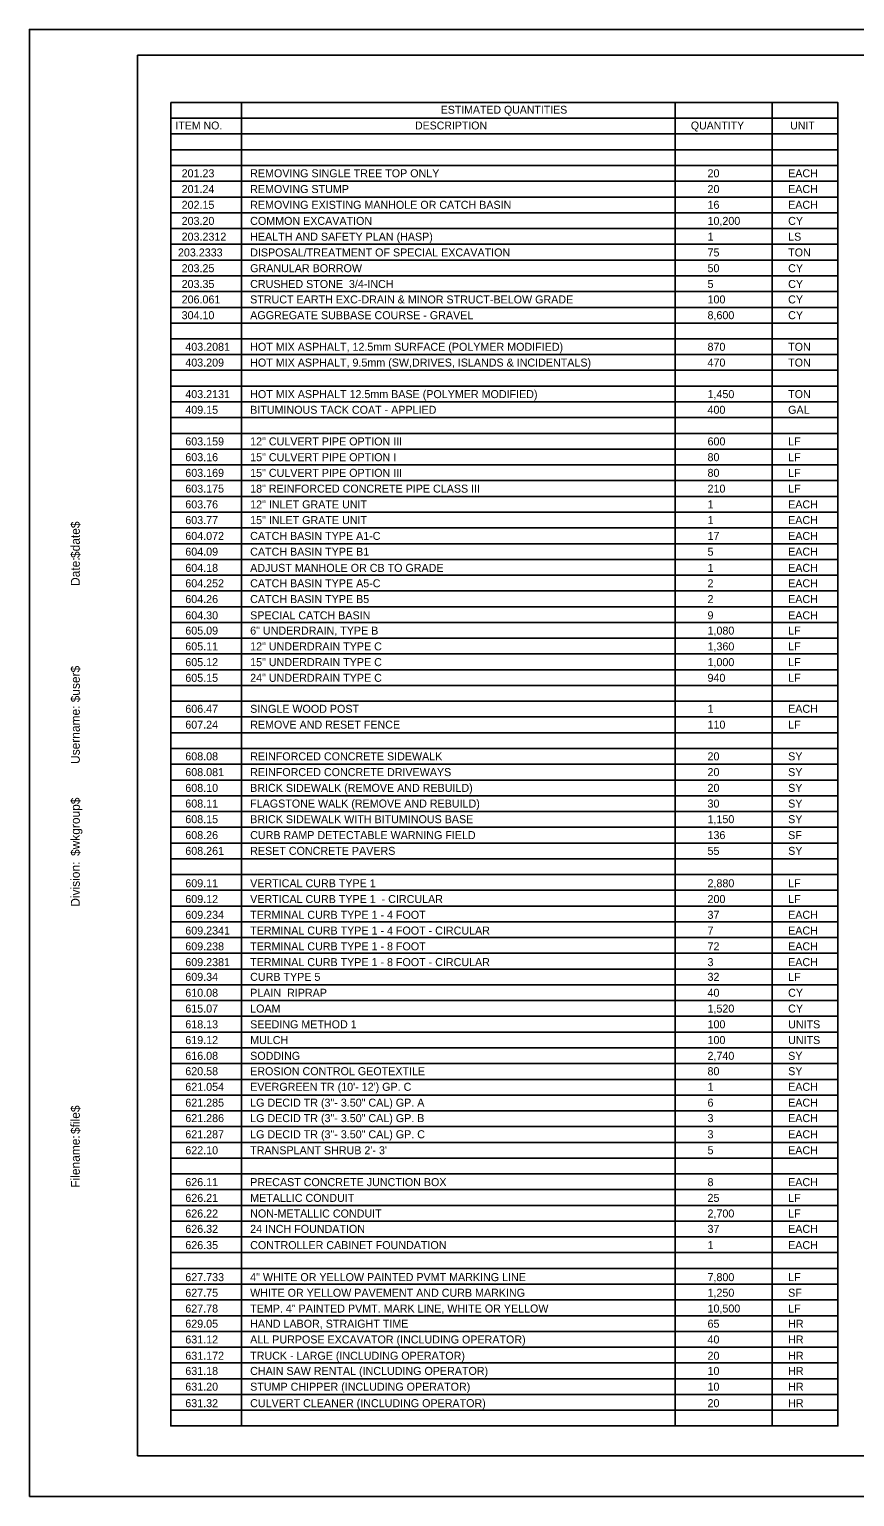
# Model space of a CAD drawing. Extents: x -0.13 to 2.7, y -0.05 to 1.78.
# Drawn here: x -0.135 to 0.896, y -0.051 to 1.782 of the extents above; entities that cross this region are included whole.
import ezdxf

# ---------------------------------------------------------------- set-up
doc = ezdxf.new("R2010")
doc.units = 0
for name, color, linetype in [('ANNOTATION', 7, 'Continuous'), ('BORDER', 7, 'Continuous'), ('PLOT BOUNDARY', 7, 'Continuous')]:
    doc.layers.add(name, color=color, linetype=linetype)

msp = doc.modelspace()

# ---------------------------------------------------------------- linework, layer by layer
at = {"layer": 'BORDER'}
for p, q in [((2.6667, 1.75), (0, 1.75)), ((0, 1.75), (0, 0)), ((0.1302, 1.6909), (0.1302, 0.0373)), ((0.6716, 1.6909), (0.6716, 0.0373)), ((0.793, 1.6909), (0.793, 0.0373)), ((0.0417, 1.6713), (0.875, 1.6713)), ((0.0417, 1.6516), (0.875, 1.6516)), ((0.0417, 1.6319), (0.875, 1.6319)), ((0.0417, 1.6122), (0.875, 1.6122)), ((0.0417, 1.5925), (0.875, 1.5925)), ((0.0417, 1.5728), (0.875, 1.5728)), ((0.0417, 1.5531), (0.875, 1.5531)), ((0.0417, 1.5335), (0.875, 1.5335)), ((0.0417, 1.5138), (0.875, 1.5138)), ((0.0417, 1.4941), (0.875, 1.4941)), ((0.0417, 1.4744), (0.875, 1.4744)), ((0.0417, 1.4547), (0.875, 1.4547)), ((0.0417, 1.435), (0.875, 1.435)), ((0.0417, 1.4153), (0.875, 1.4153)), ((0.0417, 1.3957), (0.875, 1.3957)), ((0.0417, 1.376), (0.875, 1.376)), ((0.0417, 1.3563), (0.875, 1.3563)), ((0.0417, 1.3366), (0.875, 1.3366)), ((0.0417, 1.3169), (0.875, 1.3169)), ((0.0417, 1.2972), (0.875, 1.2972)), ((0.0417, 1.2775), (0.875, 1.2775)), ((0.0417, 1.2579), (0.875, 1.2579)), ((0.0417, 1.2382), (0.875, 1.2382)), ((0.0417, 1.2185), (0.875, 1.2185)), ((0.0417, 1.1988), (0.875, 1.1988)), ((0.0417, 1.1791), (0.875, 1.1791)), ((0.0417, 1.1594), (0.875, 1.1594)), ((0.0417, 1.1397), (0.875, 1.1397)), ((0.0417, 1.12), (0.875, 1.12)), ((0.0417, 1.1004), (0.875, 1.1004)), ((0.0417, 1.0807), (0.875, 1.0807)), ((0.0417, 1.061), (0.875, 1.061)), ((0.0417, 1.0413), (0.875, 1.0413)), ((0.0417, 1.0216), (0.875, 1.0216)), ((0.0417, 1.0019), (0.875, 1.0019)), ((0.0417, 0.9822), (0.875, 0.9822)), ((0.0417, 0.9626), (0.875, 0.9626)), ((0.0417, 0.9429), (0.875, 0.9429)), ((0.0417, 0.9232), (0.875, 0.9232)), ((0.0417, 0.9035), (0.875, 0.9035)), ((0.0417, 0.8838), (0.875, 0.8838)), ((0.0417, 0.8641), (0.875, 0.8641)), ((0.0417, 0.8444), (0.875, 0.8444)), ((0.0417, 0.8248), (0.875, 0.8248)), ((0.0417, 0.8051), (0.875, 0.8051)), ((0.0417, 0.7854), (0.875, 0.7854)), ((0.0417, 0.7657), (0.875, 0.7657)), ((0.0417, 0.746), (0.875, 0.746)), ((0.0417, 0.7263), (0.875, 0.7263)), ((0.0417, 0.7066), (0.875, 0.7066)), ((0.0417, 0.687), (0.875, 0.687)), ((0.0417, 0.6673), (0.875, 0.6673)), ((0.0417, 0.6476), (0.875, 0.6476)), ((0.0417, 0.6279), (0.875, 0.6279)), ((0.0417, 0.6082), (0.875, 0.6082)), ((0.0417, 0.5885), (0.875, 0.5885)), ((0.0417, 0.5688), (0.875, 0.5688)), ((0.0417, 0.5492), (0.875, 0.5492)), ((0.0417, 0.5295), (0.875, 0.5295)), ((0.0417, 0.5098), (0.875, 0.5098)), ((0.0417, 0.4901), (0.875, 0.4901)), ((0.0417, 0.4704), (0.875, 0.4704)), ((0.0417, 0.4507), (0.875, 0.4507)), ((0.0417, 0.431), (0.875, 0.431)), ((0.0417, 0.4114), (0.875, 0.4114)), ((0.0417, 0.3917), (0.875, 0.3917)), ((0.0417, 0.372), (0.875, 0.372)), ((0.0417, 0.3523), (0.875, 0.3523)), ((0.0417, 0.3326), (0.875, 0.3326)), ((0.0417, 0.3129), (0.875, 0.3129)), ((0.0417, 0.2932), (0.875, 0.2932)), ((0.0417, 0.2736), (0.875, 0.2736)), ((0.0417, 0.2539), (0.875, 0.2539)), ((0.0417, 0.2342), (0.875, 0.2342)), ((0.0417, 0.2145), (0.875, 0.2145)), ((0.0417, 0.1948), (0.875, 0.1948)), ((0.0417, 0.1751), (0.875, 0.1751)), ((0.0417, 0.1554), (0.875, 0.1554)), ((0.0417, 0.1357), (0.875, 0.1357)), ((0.0417, 0.1161), (0.875, 0.1161)), ((0.0417, 0.0964), (0.875, 0.0964)), ((0.0417, 0.0767), (0.875, 0.0767)), ((0.0417, 0.057), (0.875, 0.057)), ((0, 0), (2.6667, 0))]:
    msp.add_line(p, q, dxfattribs=at)
msp.add_lwpolyline([(0.0417, 1.6909), (0.875, 1.6909), (0.875, 0.0373), (0.0417, 0.0373)], close=True, dxfattribs=at)
at = {"layer": 'PLOT BOUNDARY'}
msp.add_lwpolyline([(-0.1349, -0.051), (2.6984, -0.051), (2.6984, 1.7823), (-0.1349, 1.7823)], close=True, dxfattribs=at)

# ---------------------------------------------------------------- texts
at = {"layer": 'ANNOTATION'}
for s, p in [('201.23', (0.0553, 1.5975)), ('REMOVING SINGLE TREE TOP ONLY', (0.1409, 1.5975)), ('20', (0.7121, 1.5975)), ('EACH', (0.8128, 1.5975)), ('201.24', (0.0553, 1.5778)), ('REMOVING STUMP', (0.1409, 1.5778)), ('20', (0.7121, 1.5778)), ('EACH', (0.8128, 1.5778)), ('202.15', (0.0553, 1.5581)), ('REMOVING EXISTING MANHOLE OR CATCH BASIN', (0.1409, 1.5581)), ('16', (0.7121, 1.5581)), ('EACH', (0.8128, 1.5581)), ('203.20', (0.0553, 1.538)), ('COMMON EXCAVATION', (0.1409, 1.538)), ('10,200', (0.7121, 1.538)), ('CY', (0.8128, 1.538)), ('203.2312', (0.0553, 1.5183)), ('HEALTH AND SAFETY PLAN (HASP)', (0.1409, 1.5183)), ('1', (0.7121, 1.5183)), ('LS', (0.8128, 1.5183)), ('203.2333', (0.0507, 1.4986)), ('DISPOSAL/TREATMENT OF SPECIAL EXCAVATION', (0.1409, 1.4986)), ('75', (0.7121, 1.4986)), ('TON', (0.8128, 1.4986)), ('203.25', (0.0553, 1.4789)), ('GRANULAR BORROW', (0.1409, 1.4789)), ('50', (0.7121, 1.4789)), ('CY', (0.8128, 1.4789)), ('203.35', (0.0553, 1.4592)), ('CRUSHED STONE  3/4-INCH', (0.1409, 1.4592)), ('5', (0.7121, 1.4592)), ('CY', (0.8128, 1.4592)), ('206.061', (0.0553, 1.4399)), ('STRUCT EARTH EXC-DRAIN & MINOR STRUCT-BELOW GRADE', (0.1409, 1.4399)), ('100', (0.7121, 1.4399)), ('CY', (0.8128, 1.4399)), ('304.10', (0.0553, 1.4202)), ('AGGREGATE SUBBASE COURSE - GRAVEL', (0.1409, 1.4202)), ('8,600', (0.7121, 1.4202)), ('CY', (0.8128, 1.4202)), ('403.2081', (0.0599, 1.3807)), ('HOT MIX ASPHALT, 12.5mm SURFACE (POLYMER MODIFIED)', (0.1409, 1.3807)), ('870', (0.7121, 1.3807)), ('TON', (0.8128, 1.3807)), ('403.209', (0.0599, 1.361)), ('HOT MIX ASPHALT, 9.5mm (SW,DRIVES, ISLANDS & INCIDENTALS)', (0.1409, 1.361)), ('470', (0.7121, 1.361)), ('TON', (0.8128, 1.361)), ('403.2131', (0.0599, 1.3216)), ('HOT MIX ASPHALT 12.5mm BASE (POLYMER MODIFIED)', (0.1409, 1.3216)), ('1,450', (0.7121, 1.3216)), ('TON', (0.8128, 1.3216)), ('409.15', (0.0599, 1.302)), ('BITUMINOUS TACK COAT - APPLIED', (0.1409, 1.302)), ('400', (0.7121, 1.302)), ('GAL', (0.8128, 1.302)), ('603.159', (0.0599, 1.2625)), ('12" CULVERT PIPE OPTION III', (0.1409, 1.2625)), ('600', (0.7121, 1.2625)), ('LF', (0.8128, 1.2625)), ('603.16', (0.0599, 1.2428)), ('15" CULVERT PIPE OPTION I', (0.1409, 1.2428)), ('80', (0.7121, 1.2428)), ('LF', (0.8128, 1.2428)), ('603.169', (0.0599, 1.2232)), ('15" CULVERT PIPE OPTION III', (0.1409, 1.2232)), ('80', (0.7121, 1.2232)), ('LF', (0.8128, 1.2232)), ('603.175', (0.0599, 1.2035)), ('18" REINFORCED CONCRETE PIPE CLASS III', (0.1409, 1.2035)), ('210', (0.7121, 1.2035)), ('LF', (0.8128, 1.2035)), ('603.76', (0.0599, 1.1838)), ('12" INLET GRATE UNIT', (0.1409, 1.1838)), ('1', (0.7121, 1.1838)), ('EACH', (0.8128, 1.1838)), ('603.77', (0.0599, 1.1642)), ('15" INLET GRATE UNIT', (0.1409, 1.1642)), ('1', (0.7121, 1.1642)), ('EACH', (0.8128, 1.1642)), ('604.072', (0.0599, 1.1444)), ('CATCH BASIN TYPE A1-C', (0.1409, 1.1444)), ('17', (0.7121, 1.1444)), ('EACH', (0.8128, 1.1444)), ('604.09', (0.0599, 1.1247)), ('CATCH BASIN TYPE B1', (0.1409, 1.1247)), ('5', (0.7121, 1.1247)), ('EACH', (0.8128, 1.1247)), ('604.18', (0.0599, 1.1045)), ('ADJUST MANHOLE OR CB TO GRADE', (0.1409, 1.1045)), ('1', (0.7121, 1.1045)), ('EACH', (0.8128, 1.1045)), ('604.252', (0.0599, 1.0852)), ('CATCH BASIN TYPE A5-C', (0.1409, 1.0852)), ('2', (0.7121, 1.0852)), ('EACH', (0.8128, 1.0852)), ('604.26', (0.0599, 1.0655)), ('CATCH BASIN TYPE B5', (0.1409, 1.0655)), ('2', (0.7121, 1.0655)), ('EACH', (0.8128, 1.0655)), ('604.30', (0.0599, 1.0452)), ('SPECIAL CATCH BASIN', (0.1409, 1.0452)), ('9', (0.7121, 1.0452)), ('EACH', (0.8128, 1.0452)), ('605.09', (0.0599, 1.0261)), ('6" UNDERDRAIN, TYPE B', (0.1409, 1.0261)), ('1,080', (0.7121, 1.0261)), ('LF', (0.8128, 1.0261)), ('605.11', (0.0599, 1.0064)), ('12" UNDERDRAIN TYPE C', (0.1409, 1.0064)), ('1,360', (0.7121, 1.0064)), ('LF', (0.8128, 1.0064)), ('605.12', (0.0599, 0.9867)), ('15" UNDERDRAIN TYPE C', (0.1409, 0.9867)), ('1,000', (0.7121, 0.9867)), ('LF', (0.8128, 0.9867)), ('605.15', (0.0599, 0.9671)), ('24" UNDERDRAIN TYPE C', (0.1409, 0.9671)), ('940', (0.7121, 0.9671)), ('LF', (0.8128, 0.9671)), ('606.47', (0.0599, 0.9284)), ('SINGLE WOOD POST', (0.1409, 0.9284)), ('1', (0.7121, 0.9284)), ('EACH', (0.8128, 0.9284)), ('607.24', (0.0599, 0.9086)), ('REMOVE AND RESET FENCE', (0.1409, 0.9086)), ('110', (0.7121, 0.9086)), ('LF', (0.8128, 0.9086)), ('608.08', (0.0599, 0.869)), ('REINFORCED CONCRETE SIDEWALK', (0.1409, 0.869)), ('20', (0.7121, 0.869)), ('SY', (0.8128, 0.869)), ('608.081', (0.0599, 0.8493)), ('REINFORCED CONCRETE DRIVEWAYS', (0.1409, 0.8493)), ('20', (0.7121, 0.8493)), ('SY', (0.8128, 0.8493)), ('608.10', (0.0599, 0.8296)), ('BRICK SIDEWALK (REMOVE AND REBUILD)', (0.1409, 0.8296)), ('20', (0.7121, 0.8296)), ('SY', (0.8128, 0.8296)), ('608.11', (0.0599, 0.81)), ('FLAGSTONE WALK (REMOVE AND REBUILD)', (0.1409, 0.81)), ('30', (0.7121, 0.81)), ('SY', (0.8128, 0.81)), ('608.15', (0.0599, 0.7905)), ('BRICK SIDEWALK WITH BITUMINOUS BASE', (0.1409, 0.7905)), ('1,150', (0.7121, 0.7905)), ('SY', (0.8128, 0.7905)), ('608.26', (0.0599, 0.7706)), ('CURB RAMP DETECTABLE WARNING FIELD', (0.1409, 0.7706)), ('136', (0.7121, 0.7706)), ('SF', (0.8128, 0.7706)), ('608.261', (0.0599, 0.7509)), ('RESET CONCRETE PAVERS', (0.1409, 0.7509)), ('55', (0.7121, 0.7509)), ('SY', (0.8128, 0.7509)), ('609.11', (0.0599, 0.7104)), ('VERTICAL CURB TYPE 1', (0.1409, 0.7104)), ('2,880', (0.7121, 0.7104)), ('LF', (0.8128, 0.7104)), ('609.12', (0.0599, 0.6907)), ('VERTICAL CURB TYPE 1  - CIRCULAR', (0.1409, 0.6907)), ('200', (0.7121, 0.6907)), ('LF', (0.8128, 0.6907)), ('609.234', (0.0599, 0.671)), ('TERMINAL CURB TYPE 1 - 4 FOOT', (0.1409, 0.671)), ('37', (0.7121, 0.671)), ('EACH', (0.8128, 0.671)), ('609.2341', (0.0599, 0.6513)), ('TERMINAL CURB TYPE 1 - 4 FOOT - CIRCULAR', (0.1409, 0.6513)), ('7', (0.7121, 0.6513)), ('EACH', (0.8128, 0.6513)), ('609.238', (0.0599, 0.6316)), ('TERMINAL CURB TYPE 1 - 8 FOOT', (0.1409, 0.6316)), ('72', (0.7121, 0.6316)), ('EACH', (0.8128, 0.6316)), ('609.2381', (0.0599, 0.6119)), ('TERMINAL CURB TYPE 1 - 8 FOOT - CIRCULAR', (0.1409, 0.6119)), ('3', (0.7121, 0.6119)), ('EACH', (0.8128, 0.6119)), ('609.34', (0.0599, 0.5935)), ('CURB TYPE 5', (0.1409, 0.5935)), ('32', (0.7121, 0.5935)), ('LF', (0.8128, 0.5935)), ('610.08', (0.0599, 0.5736)), ('PLAIN  RIPRAP', (0.1409, 0.5736)), ('40', (0.7121, 0.5736)), ('CY', (0.8128, 0.5736)), ('615.07', (0.0599, 0.5539)), ('LOAM', (0.1409, 0.5539)), ('1,520', (0.7121, 0.5539)), ('CY', (0.8128, 0.5539)), ('618.13', (0.0599, 0.5342)), ('SEEDING METHOD 1', (0.1409, 0.5342)), ('100', (0.7121, 0.5342)), ('UNITS', (0.8128, 0.5342)), ('619.12', (0.0599, 0.5145)), ('MULCH', (0.1409, 0.5145)), ('100', (0.7121, 0.5145)), ('UNITS', (0.8128, 0.5145)), ('616.08', (0.0599, 0.4948)), ('SODDING', (0.1409, 0.4948)), ('2,740', (0.7121, 0.4948)), ('SY', (0.8128, 0.4948)), ('620.58', (0.0599, 0.4756)), ('EROSION CONTROL GEOTEXTILE', (0.1409, 0.4756)), ('80', (0.7121, 0.4756)), ('SY', (0.8128, 0.4756)), ('621.054', (0.0599, 0.4561)), ("EVERGREEN TR (10'- 12') GP. C", (0.1409, 0.4561)), ('1', (0.7121, 0.4561)), ('EACH', (0.8128, 0.4561)), ('621.285', (0.0599, 0.4363)), ('LG DECID TR (3"- 3.50" CAL) GP. A', (0.1409, 0.4363)), ('6', (0.7121, 0.4363)), ('EACH', (0.8128, 0.4363)), ('621.286', (0.0599, 0.417)), ('LG DECID TR (3"- 3.50" CAL) GP. B', (0.1409, 0.417)), ('3', (0.7121, 0.417)), ('EACH', (0.8128, 0.417)), ('621.287', (0.0599, 0.3968)), ('LG DECID TR (3"- 3.50" CAL) GP. C', (0.1409, 0.3968)), ('3', (0.7121, 0.3968)), ('EACH', (0.8128, 0.3968)), ('622.10', (0.0599, 0.3768)), ("TRANSPLANT SHRUB 2'- 3'", (0.1409, 0.3768)), ('5', (0.7121, 0.3768)), ('EACH', (0.8128, 0.3768)), ('626.11', (0.0599, 0.337)), ('PRECAST CONCRETE JUNCTION BOX', (0.1409, 0.337)), ('8', (0.7121, 0.337)), ('EACH', (0.8128, 0.337)), ('626.21', (0.0599, 0.3173)), ('METALLIC CONDUIT', (0.1409, 0.3173)), ('25', (0.7121, 0.3173)), ('LF', (0.8128, 0.3173)), ('626.22', (0.0599, 0.2978)), ('NON-METALLIC CONDUIT', (0.1409, 0.2978)), ('2,700', (0.7121, 0.2978)), ('LF', (0.8128, 0.2978)), ('626.32', (0.0599, 0.2786)), ('24 INCH FOUNDATION', (0.1409, 0.2786)), ('37', (0.7121, 0.2786)), ('EACH', (0.8128, 0.2786)), ('626.35', (0.0599, 0.2583)), ('CONTROLLER CABINET FOUNDATION', (0.1409, 0.2583)), ('1', (0.7121, 0.2583)), ('EACH', (0.8128, 0.2583)), ('627.733', (0.0599, 0.2183)), ('4" WHITE OR YELLOW PAINTED PVMT MARKING LINE ', (0.1409, 0.2183)), ('7,800', (0.7121, 0.2183)), ('LF', (0.8128, 0.2183)), ('627.75', (0.0599, 0.1988)), ('WHITE OR YELLOW PAVEMENT AND CURB MARKING', (0.1409, 0.1988)), ('1,250', (0.7121, 0.1988)), ('SF', (0.8128, 0.1988)), ('627.78', (0.0599, 0.1791)), ('TEMP. 4" PAINTED PVMT. MARK LINE, WHITE OR YELLOW', (0.1409, 0.1791)), ('10,500', (0.7121, 0.1791)), ('LF', (0.8128, 0.1791)), ('629.05', (0.0599, 0.1601)), ('HAND LABOR, STRAIGHT TIME', (0.1409, 0.1601)), ('65', (0.7121, 0.1601)), ('HR', (0.8128, 0.1601)), ('631.12', (0.0599, 0.1404)), ('ALL PURPOSE EXCAVATOR (INCLUDING OPERATOR)', (0.1409, 0.1404)), ('40', (0.7121, 0.1404)), ('HR', (0.8128, 0.1404)), ('631.172', (0.0599, 0.1201)), ('TRUCK - LARGE (INCLUDING OPERATOR)', (0.1409, 0.1201)), ('20', (0.7121, 0.1201)), ('HR', (0.8128, 0.1201)), ('631.18', (0.0599, 0.1011)), ('CHAIN SAW RENTAL (INCLUDING OPERATOR)', (0.1409, 0.1011)), ('10', (0.7121, 0.1011)), ('HR', (0.8128, 0.1011)), ('STUMP CHIPPER (INCLUDING OPERATOR)', (0.1409, 0.0814)), ('631.20', (0.0599, 0.0814)), ('10', (0.7121, 0.0814)), ('HR', (0.8128, 0.0814)), ('631.32', (0.0599, 0.0608)), ('CULVERT CLEANER (INCLUDING OPERATOR)', (0.1409, 0.0608)), ('20', (0.7121, 0.0608)), ('HR', (0.8128, 0.0608))]:
    msp.add_text(s, height=0.01, dxfattribs=at).set_placement(p)
at = {"layer": 'BORDER'}
for s, height, p in [('ESTIMATED QUANTITIES', 0.009843, (0.3789, 1.677)), ('ITEM NO.', 0.00984, (0.0476, 1.6573)), ('DESCRIPTION', 0.009843, (0.3468, 1.6573)), ('QUANTITY', 0.00984, (0.6913, 1.6573)), ('UNIT', 0.00984, (0.8153, 1.6573))]:
    msp.add_text(s, height=height, dxfattribs=at).set_placement(p)
for s, p in [('$date$', (-0.0719, 1.1218)), ('Date:', (-0.0719, 1.0869)), ('$user$', (-0.0719, 0.9415)), ('Username:', (-0.0719, 0.8645)), ('$wkgroup$', (-0.0719, 0.7495)), ('Division:', (-0.0719, 0.6861)), ('$file$', (-0.0719, 0.4021)), ('Filename:', (-0.0719, 0.335))]:
    msp.add_text(s, height=0.01116, rotation=90, dxfattribs=at).set_placement(p)

doc.saveas('drawing.dxf')
